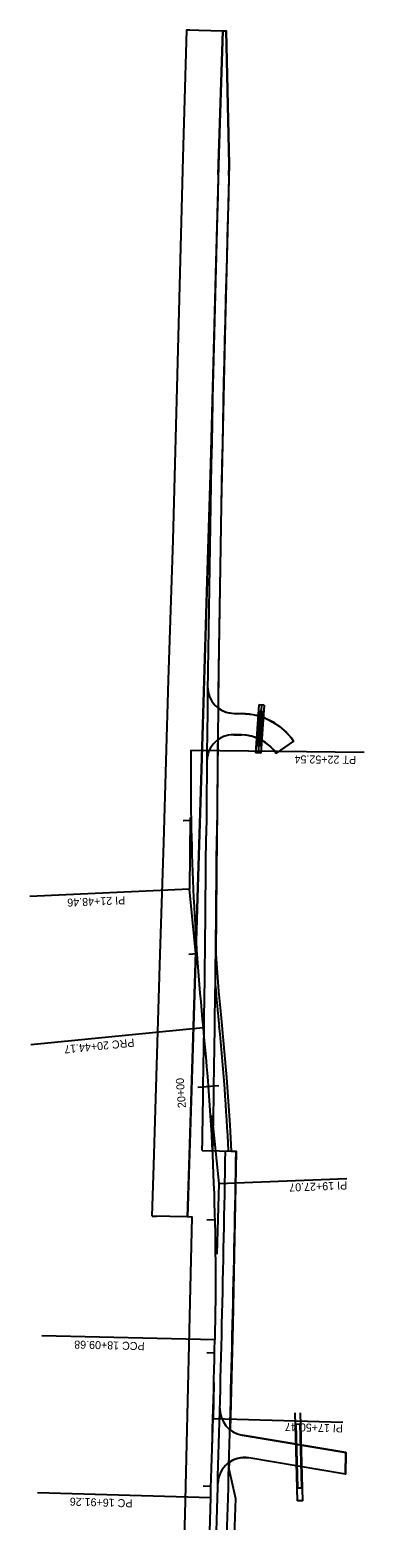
# Model space of a CAD drawing. Extents: x 1445613 to 1446340, y 2042797 to 2056486.
# Drawn here: x 1446000 to 1446251, y 2044179 to 2045297 of the extents above; entities that cross this region are included whole.
import ezdxf

# ---------------------------------------------------------------- set-up
doc = ezdxf.new("R2010")
doc.units = 0
for name, color, linetype in [('20', 7, 'Continuous'), ('Default', 7, 'Continuous'), ('Level 43', 7, 'Continuous'), ('R_Horz Alg', 7, 'Continuous'), ('R_Horz Alg Annot', 7, 'Continuous'), ('R_Horz Alg Stationing', 7, 'Continuous'), ('R_Proposed Road', 7, 'Continuous')]:
    doc.layers.add(name, color=color, linetype=linetype)

msp = doc.modelspace()

# ---------------------------------------------------------------- linework, layer by layer
at = {"layer": '20'}
msp.add_lwpolyline([(1446091.7, 2044407.2), (1446092.9, 2044445.6), (1446097.7, 2044603.7), (1446100.3, 2044687.5), (1446103.8, 2044809.4), (1446107.3, 2044914.2), (1446112.2, 2045095.5), (1446115, 2045201.2), (1446117.7, 2045297), (1446144.6, 2045296.2), (1446141.5, 2045196.2), (1446137.2, 2045030.2), (1446134.7, 2044942.3), (1446128.2, 2044726), (1446122.7, 2044549.5), (1446118.1, 2044406.7)], close=True, dxfattribs=at)
msp.add_lwpolyline([(1446112, 2044036.7), (1446116.3, 2044183.6), (1446121.8, 2044406.6), (1446118.1, 2044406.7), (1446119.6, 2044453.1), (1446122.7, 2044549.5), (1446128.2, 2044726), (1446132.7, 2044875.2), (1446135.6, 2044971.4), (1446139.6, 2045122.9), (1446143.4, 2045257.1), (1446144.6, 2045296.2), (1446147.2, 2045296.1), (1446149.5, 2045196), (1446146.1, 2045066.9), (1446143.4, 2044940.2), (1446141.5, 2044817.8), (1446141.1, 2044788.5), (1446143.7, 2044786.8), (1446147, 2044785.3), (1446150.1, 2044784.6), (1446153.1, 2044784.3), (1446158.8, 2044784.2), (1446167.1, 2044783.4), (1446173.1, 2044781.9), (1446177, 2044780.5), (1446182.3, 2044777.8), (1446187, 2044774.7), (1446192.4, 2044770), (1446195.6, 2044766.5), (1446197.8, 2044763.5), (1446184.6, 2044754.4), (1446182.9, 2044756.7), (1446180.1, 2044759.7), (1446174.8, 2044763.7), (1446167.8, 2044766.8), (1446163.4, 2044767.8), (1446158.6, 2044768.2), (1446152.9, 2044768.3), (1446149, 2044768), (1446146.1, 2044767.2), (1446143.7, 2044766.2), (1446140.9, 2044764.4), (1446140.2, 2044692.4), (1446139.4, 2044603.7), (1446141.5, 2044575.9), (1446143.1, 2044558.5), (1446147.4, 2044511.3), (1446149.9, 2044475.6), (1446150.9, 2044456.1), (1446154.7, 2044456), (1446152.1, 2044325.8), (1446150.1, 2044247), (1446152.2, 2044245.6), (1446155.4, 2044244), (1446159.2, 2044243), (1446237.1, 2044229.9), (1446236.7, 2044213.7), (1446164.3, 2044225.9), (1446159.6, 2044226.1), (1446156, 2044225.6), (1446152.7, 2044224.4), (1446149.4, 2044222.5), (1446149.3, 2044217.7), (1446154.1, 2044195.5), (1446153.3, 2044167.5)], dxfattribs=at)
at = {"layer": 'Default'}
for p, q in [((1446117.7, 2045297), (1446119.9, 2045296.9)), ((1446091.7, 2044407.2), (1446094.6, 2044407.1))]:
    msp.add_line(p, q, dxfattribs=at)
at = {"layer": 'Level 43'}
for p, q in [((1446171.6, 2044790.7), (1446169.2, 2044754.8)), ((1446173.6, 2044790.5), (1446171.2, 2044754.6)), ((1446175.6, 2044790.4), (1446171.6, 2044790.7)), ((1446175.6, 2044790.4), (1446173.2, 2044754.5)), ((1446172.6, 2044786.1), (1446170.8, 2044759.6)), ((1446174.1, 2044786), (1446172.3, 2044759.5)), ((1446174.1, 2044786), (1446172.6, 2044786.1)), ((1446173.2, 2044754.5), (1446169.2, 2044754.8)), ((1446170.8, 2044759.6), (1446172.3, 2044759.5)), ((1446200.6, 2044193.7), (1446199, 2044259.7)), ((1446199.7, 2044251.3), (1446202.7, 2044251.4)), ((1446200.9, 2044203.5), (1446199.7, 2044251.3)), ((1446203.9, 2044203.6), (1446202.7, 2044251.4)), ((1446204.6, 2044193.8), (1446203, 2044259.7)), ((1446200.9, 2044203.5), (1446203.9, 2044203.6)), ((1446204.6, 2044193.8), (1446200.6, 2044193.7))]:
    msp.add_line(p, q, dxfattribs=at)
at = {"layer": 'R_Horz Alg'}
msp.add_line((1446131, 2044036.1), (1446135.6, 2044196.1), dxfattribs=at)
for centre, radius, start, end in [((1448030.5, 2044737.1), 1909.9, 179.4129, 185.664), ((1448030.5, 2044737.1), 1897.9, 184.7183, 185.664), ((1444229.5, 2044360.1), 1909.9, 358.629, 5.664), ((1444229.5, 2044360.1), 1921.9, 2.8636, 5.664), ((1423202.5, 2044863.3), 22942.8, 358.33333, 358.62905)]:
    msp.add_arc(centre, radius, start, end, dxfattribs=at)
at = {"layer": 'R_Horz Alg Annot'}
for p, q in [((1446120.3, 2044706.3), (1446119.7, 2044652.4)), ((1446125, 2044599.2), (1446119.7, 2044652.4)), ((1446136.5, 2044482.8), (1446141.6, 2044431.8)), ((1446141.6, 2044431.8), (1446140.3, 2044378.7)), ((1446141.6, 2044431.8), (1446237.7, 2044435.4)), ((1446138, 2044282.6), (1446137.4, 2044255.2)), ((1446136.8, 2044234.2), (1446137.4, 2044255.2)), ((1446234.8, 2044252.6), (1446137.4, 2044255.2))]:
    msp.add_line(p, q, dxfattribs=at)
for points in [[(1446120.8, 2044756.7), (1446250.8, 2044755.3)], [(1446119.7, 2044652.4), (1445999.8, 2044647.1)], [(1446130, 2044548.6), (1446000.6, 2044535.8)], [(1446138.8, 2044314.4), (1446008.8, 2044317.5)], [(1446135.6, 2044196.1), (1446005.7, 2044199.8)]]:
    msp.add_lwpolyline(points, dxfattribs=at)
at = {"layer": 'R_Horz Alg Stationing'}
for points in [[(1446115, 2044704), (1446121, 2044704.1)], [(1446119.3, 2044603.8), (1446125.3, 2044604.2)], [(1446125.9, 2044504), (1446141.8, 2044505.2)], [(1446132.8, 2044404.6), (1446138.8, 2044404.7)], [(1446132.6, 2044304.9), (1446138.6, 2044304.7)], [(1446129.9, 2044205), (1446135.9, 2044204.8)]]:
    msp.add_lwpolyline(points, dxfattribs=at)
at = {"layer": 'R_Proposed Road'}
for p, q in [((1446141.5, 2045196.2), (1446144.6, 2045296.2)), ((1446149.5, 2045196), (1446147.2, 2045296.1)), ((1446141.3, 2045188.1), (1446141.5, 2045196.2)), ((1446149.3, 2045187.8), (1446149.5, 2045196)), ((1446153.1, 2044784.3), (1446158.8, 2044784.2)), ((1446152.9, 2044768.3), (1446158.6, 2044768.2)), ((1446197.8, 2044763.5), (1446184.6, 2044754.4)), ((1446129.2, 2044456.5), (1446154.7, 2044456)), ((1446237.1, 2044229.9), (1446159.2, 2044243)), ((1446236.7, 2044213.7), (1446237.1, 2044229.9)), ((1446236.7, 2044213.7), (1446164.3, 2044225.9)), ((1446136, 2044036), (1446140.6, 2044195.9)), ((1446147.8, 2044167.7), (1446148.6, 2044195.7))]:
    msp.add_line(p, q, dxfattribs=at)
for centre, radius, start, end in [((1469037.9, 2044521.8), 22906.3, 178.33333, 179.57311), ((1469037.9, 2044521.8), 22898.3, 178.33333, 179.57311), ((1446153.3, 2044804.3), 20, 179.2928, 269.3629), ((1446158.3, 2044736.2), 48, 34.5357, 89.3629), ((1446152.7, 2044748.3), 20, 89.3629, 179.433), ((1446158.3, 2044736.2), 32, 34.5357, 89.3629), ((1423202.5, 2044863.3), 22930.3, 358.98333, 359.57311), ((1423202.5, 2044863.3), 22938.3, 358.98333, 359.57311), ((1423202.5, 2044863.3), 22947.8, 358.33333, 358.98333), ((1423202.5, 2044863.3), 22955.8, 358.33333, 358.98333), ((1446162.5, 2044262.7), 20, 178.5015, 260.4483), ((1446160.9, 2044206.2), 20, 80.4483, 178.3605)]:
    msp.add_arc(centre, radius, start, end, dxfattribs=at)

# ---------------------------------------------------------------- texts
at = {"layer": 'R_Horz Alg Annot'}
for s, rotation, p in [('PT 22+52.54', 179.4129, (1446244.7, 2044752.4)), ('PI 21+48.46', 182.5384, (1446071.3, 2044647.2)), ('PRC 20+44.17', 185.664, (1446078, 2044540.4)), ('PI 19+27.07', 182.1489, (1446237.9, 2044433.3)), ('PI 19+27.07', 182.1489, (1446237.9, 2044433.3)), ('PI 19+27.07', 182.1489, (1446237.9, 2044433.3)), ('PCC 18+09.68', 178.629, (1446086.1, 2044312.7)), ('PI 17+50.47', 178.4866, (1446234.9, 2044251)), ('PC 16+91.26', 178.3333, (1446077, 2044194.8))]:
    msp.add_text(s, height=6, rotation=rotation, dxfattribs=at).set_placement(p)
at = {"layer": 'R_Horz Alg Stationing'}
msp.add_text('20+00', height=6, rotation=94.3388, dxfattribs=at).set_placement((1446117, 2044488.6))

doc.saveas('drawing.dxf')
